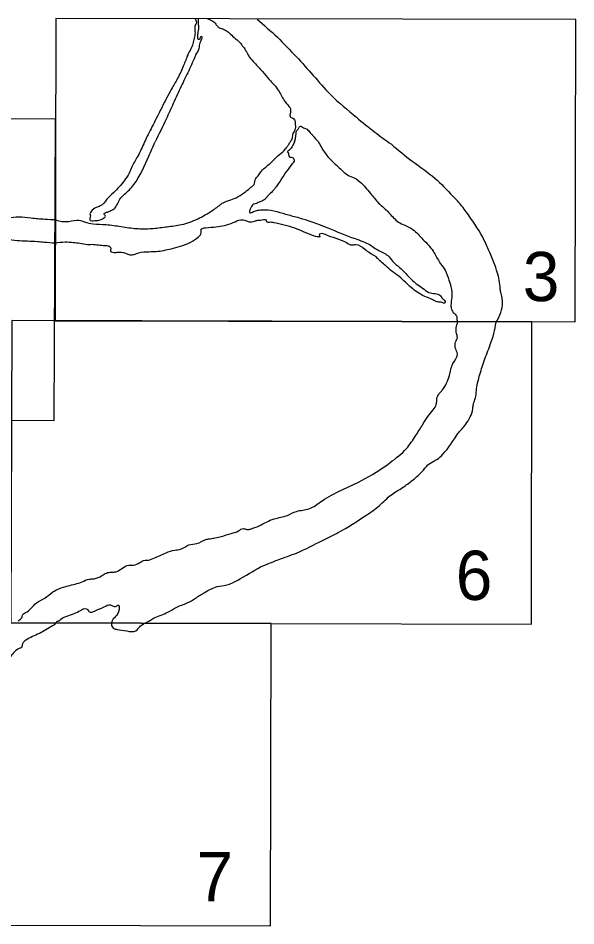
# Model space of a CAD drawing. Extents: x 3148686 to 3186545, y 916144 to 941516.
# Drawn here: x 3174711 to 3176037, y 918387 to 920544 of the extents above; entities that cross this region are included whole.
import ezdxf

# ---------------------------------------------------------------- set-up
doc = ezdxf.new("R2010")
doc.units = 0
doc.layers.add('V-ANNO-NPLT', color=7, linetype='Continuous')

msp = doc.modelspace()

# ---------------------------------------------------------------- linework, layer by layer
at = {"layer": 'V-ANNO-NPLT'}
for points in [[(3176036.1228912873, 919822.4712113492), (3176037.428891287, 920540.8912113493), (3174801.016891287, 920543.6782113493), (3174799.0828912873, 919825.2592113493), (3176036.1228912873, 919822.4712113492)], [(3173561.1928912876, 919589.6592113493), (3174796.979891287, 919588.3572113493), (3174800.3718912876, 920304.2032113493), (3173563.7538912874, 920308.0702113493), (3173561.1928912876, 919589.6592113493)], [(3174694.0118912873, 919107.1392113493), (3175931.6778912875, 919104.2592113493), (3175933.0358912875, 919822.6622113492), (3174695.9968912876, 919825.5412113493), (3174694.0118912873, 919107.1392113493)], [(3174072.8808912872, 918390.6002113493), (3175311.1728912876, 918387.1782113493), (3175312.843891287, 919105.5642113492), (3174694.0118912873, 919107.2742113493)]]:
    msp.add_lwpolyline(points, dxfattribs=at)
for points in [[(3175132.5218912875, 920542.8872113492), (3175133.1628912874, 920541.5342113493), (3175135.0408912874, 920533.0772113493), (3175131.7548912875, 920526.5002113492), (3175131.2858912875, 920519.9222113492), (3175131.7548912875, 920506.2972113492), (3175129.408891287, 920493.6122113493), (3175125.6538912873, 920479.9872113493), (3175118.144891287, 920464.0142113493), (3175112.0438912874, 920451.3282113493)], [(3175133.6328912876, 920457.4362113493), (3175141.610891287, 920472.0012113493), (3175143.9578912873, 920486.0952113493), (3175147.7118912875, 920494.5522113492), (3175148.6508912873, 920499.7202113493), (3175147.2428912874, 920500.1902113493), (3175144.4268912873, 920498.7802113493), (3175143.0188912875, 920495.4922113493), (3175140.2028912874, 920493.6122113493), (3175138.7948912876, 920495.4922113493), (3175138.7948912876, 920499.7202113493), (3175138.7948912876, 920503.4792113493), (3175139.7338912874, 920514.7542113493), (3175141.141891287, 920523.6812113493), (3175140.2028912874, 920528.8492113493), (3175139.7338912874, 920534.4872113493), (3175140.2028912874, 920538.7152113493), (3175139.7338912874, 920542.0042113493), (3175139.2648912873, 920544.3532113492), (3175139.2598912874, 920544.4462113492)], [(3175160.4308912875, 920543.4462113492), (3175167.8928912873, 920540.1252113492), (3175174.462891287, 920537.3062113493), (3175178.2178912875, 920534.0172113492), (3175183.8498912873, 920526.9702113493), (3175189.4808912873, 920521.8022113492), (3175199.8058912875, 920518.0432113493), (3175208.7228912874, 920512.8752113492), (3175219.0478912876, 920503.9482113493), (3175231.7198912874, 920492.6732113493), (3175238.7598912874, 920486.5652113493), (3175242.0448912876, 920481.8672113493), (3175246.7378912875, 920475.7592113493), (3175252.8388912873, 920467.3022113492), (3175256.593891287, 920460.2552113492), (3175260.3478912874, 920452.2682113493)], [(3175279.252891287, 920542.2832113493), (3175327.7588912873, 920498.9082113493), (3175372.5578912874, 920452.9942113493), (3175413.0888912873, 920408.1482113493), (3175453.6208912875, 920363.3012113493), (3175515.485891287, 920308.8442113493), (3175559.2178912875, 920273.6082113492), (3175598.6828912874, 920244.7782113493)], [(3175114.965891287, 920457.4032113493), (3175104.5348912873, 920431.5962113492), (3175090.4558912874, 920401.5272113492), (3175075.4368912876, 920375.2172113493), (3175064.1738912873, 920354.5452113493), (3175050.093891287, 920326.3562113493), (3175029.4438912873, 920285.9512113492), (3175011.6098912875, 920250.2452113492)], [(3175133.6888912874, 920457.5382113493), (3175116.7368912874, 920419.3812113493), (3175098.9028912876, 920382.7342113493), (3175080.1308912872, 920341.3902113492), (3175063.2348912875, 920304.7442113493), (3175036.9538912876, 920250.2452113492)], [(3175260.3478912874, 920452.2682113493), (3175273.4888912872, 920438.1732113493), (3175292.2618912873, 920417.5012113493), (3175308.2178912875, 920398.7082113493), (3175329.806891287, 920373.3382113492), (3175343.8868912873, 920348.9072113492), (3175355.1498912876, 920334.8132113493), (3175357.965891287, 920331.0542113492), (3175357.965891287, 920316.9602113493), (3175357.965891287, 920310.3822113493), (3175364.5358912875, 920306.6232113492), (3175368.2908912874, 920302.8652113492), (3175370.1678912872, 920296.2872113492), (3175370.1678912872, 920290.6502113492), (3175371.1068912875, 920287.8312113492), (3175370.1678912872, 920281.2532113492), (3175367.3518912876, 920274.6762113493), (3175364.5358912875, 920269.9772113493), (3175362.658891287, 920258.7022113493), (3175357.965891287, 920250.2452113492)], [(3175368.2908912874, 920250.2452113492), (3175371.1068912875, 920260.5812113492), (3175372.0458912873, 920269.0382113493), (3175372.9838912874, 920275.6152113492), (3175375.7998912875, 920279.3742113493), (3175379.5548912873, 920285.0122113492), (3175382.3698912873, 920287.8312113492), (3175385.1858912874, 920286.8912113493), (3175389.8798912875, 920284.0722113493), (3175398.326891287, 920280.3132113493), (3175405.8358912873, 920271.8572113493), (3175411.4678912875, 920266.2192113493), (3175416.1608912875, 920260.5812113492), (3175418.9768912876, 920256.8222113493), (3175425.5478912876, 920250.2452113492)], [(3175011.6098912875, 920250.2452113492), (3174995.6538912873, 920216.4182113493), (3174981.573891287, 920191.0472113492), (3174975.0038912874, 920176.0132113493), (3174963.7398912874, 920158.1602113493), (3174938.3968912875, 920129.9712113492), (3174922.4398912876, 920113.9972113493), (3174906.4838912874, 920098.0232113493), (3174897.0968912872, 920094.2642113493), (3174884.894891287, 920084.8682113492), (3174882.0788912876, 920079.2302113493), (3174883.0178912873, 920074.5322113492), (3174882.0788912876, 920068.8942113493), (3174882.0788912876, 920065.1352113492), (3174893.3428912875, 920063.2562113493), (3174906.4838912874, 920065.1352113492), (3174913.9928912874, 920068.8942113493), (3174918.6858912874, 920073.5922113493), (3174916.8078912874, 920077.3512113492), (3174915.8698912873, 920080.1702113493), (3174921.5018912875, 920082.9892113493), (3174929.0108912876, 920085.8082113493), (3174939.3358912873, 920091.4452113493), (3174953.414891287, 920113.9972113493), (3174975.9418912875, 920136.5482113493), (3174986.266891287, 920148.7642113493), (3175021.9348912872, 920216.4182113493), (3175036.9538912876, 920250.2452113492)], [(3175368.2908912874, 920250.2452113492), (3175360.3128912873, 920235.6802113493), (3175354.6808912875, 920230.0432113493), (3175351.8648912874, 920227.2242113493), (3175353.7418912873, 920222.5262113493), (3175354.6808912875, 920217.8272113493), (3175357.4968912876, 920214.0692113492), (3175360.3128912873, 920214.0692113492), (3175365.0058912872, 920212.1892113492), (3175367.8218912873, 920206.5522113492), (3175363.127891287, 920198.0952113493), (3175324.644891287, 920143.5962113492), (3175316.1968912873, 920133.2592113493), (3175304.9328912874, 920121.9842113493), (3175300.2398912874, 920116.3462113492), (3175294.607891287, 920111.6482113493), (3175286.1608912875, 920107.8892113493), (3175277.712891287, 920104.1312113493), (3175267.3878912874, 920099.4322113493), (3175264.5718912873, 920093.7952113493), (3175261.7558912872, 920086.2772113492), (3175261.7558912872, 920082.5192113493), (3175268.326891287, 920083.4582113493), (3175278.6518912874, 920087.2172113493), (3175290.8538912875, 920089.0962113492), (3175347.1718912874, 920078.7602113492), (3175375.3308912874, 920071.2432113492), (3175447.604891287, 920045.8732113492), (3175512.3708912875, 920020.5022113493), (3175548.0388912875, 920005.4682113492), (3175560.2408912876, 919997.0112113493)], [(3175272.5498912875, 920148.7642113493), (3175276.7738912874, 920163.3282113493), (3175283.3448912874, 920171.7852113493), (3175289.914891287, 920181.1812113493), (3175300.2398912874, 920190.5782113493), (3175319.9508912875, 920208.4312113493), (3175333.0918912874, 920220.6462113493), (3175347.1718912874, 920233.8012113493), (3175349.9878912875, 920237.5602113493), (3175354.6808912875, 920244.1372113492), (3175358.6748912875, 920251.5222113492)], [(3175425.5478912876, 920250.2452113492), (3175441.9738912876, 920222.5262113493), (3175458.8688912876, 920203.7332113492), (3175484.2118912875, 920180.2422113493), (3175494.536891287, 920171.7852113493), (3175510.4938912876, 920165.2072113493), (3175527.3888912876, 920152.0522113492), (3175536.7758912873, 920142.6562113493), (3175548.9778912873, 920127.6222113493), (3175567.7508912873, 920105.0702113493)], [(3175598.6828912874, 920244.7782113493), (3175648.4728912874, 920204.6722113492), (3175701.9748912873, 920164.2682113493), (3175744.6828912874, 920121.5142113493)], [(3174801.0798912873, 920064.7692113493), (3174815.4358912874, 920061.3772113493), (3174831.3928912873, 920061.3772113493), (3174856.735891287, 920064.1962113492), (3174868.9378912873, 920060.4372113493), (3174889.587891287, 920055.7392113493), (3174920.5628912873, 920053.8602113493), (3174956.2308912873, 920049.1612113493), (3174992.837891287, 920044.4632113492), (3175028.5058912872, 920044.4632113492), (3175061.357891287, 920048.2222113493), (3175095.1488912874, 920052.9202113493), (3175133.6328912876, 920065.1352113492), (3175169.3008912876, 920084.8682113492), (3175191.8278912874, 920100.8422113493), (3175198.397891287, 920105.5402113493), (3175212.4778912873, 920111.1782113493), (3175229.3728912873, 920117.7552113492), (3175248.1458912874, 920129.0312113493), (3175262.2248912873, 920140.3072113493), (3175272.5498912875, 920148.7642113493)], [(3175847.5928912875, 919821.8102113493), (3175859.195891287, 919845.2592113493), (3175862.9508912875, 919868.7502113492), (3175861.0728912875, 919883.7842113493), (3175858.2568912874, 919895.0602113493), (3175857.3188912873, 919906.3362113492), (3175848.8708912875, 919945.8012113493), (3175830.0978912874, 919993.7232113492), (3175816.0188912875, 920023.7912113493), (3175776.5958912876, 920083.9282113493), (3175755.945891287, 920110.2382113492), (3175744.6828912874, 920121.5142113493)], [(3175567.7508912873, 920105.0702113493), (3175593.093891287, 920081.5792113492), (3175615.6208912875, 920059.9672113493), (3175630.6388912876, 920052.4502113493), (3175649.411891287, 920042.1142113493), (3175673.8158912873, 920018.6232113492), (3175698.2198912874, 919990.4342113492), (3175712.2998912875, 919966.0032113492), (3175726.3788912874, 919945.3312113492), (3175735.7658912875, 919921.8402113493), (3175740.4588912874, 919905.8662113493), (3175742.3358912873, 919881.4352113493), (3175740.4588912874, 919862.6422113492), (3175741.397891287, 919853.2462113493), (3175747.9678912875, 919842.9102113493), (3175754.5378912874, 919834.4532113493), (3175754.5378912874, 919829.7552113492), (3175756.7098912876, 919822.8552113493)], [(3174801.0798912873, 920064.7702113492), (3174774.8388912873, 920066.1522113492), (3174741.6918912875, 920068.9172113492), (3174712.6878912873, 920071.6832113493), (3174687.8278912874, 920068.9172113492), (3174669.8738912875, 920067.5352113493), (3174654.6808912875, 920062.0042113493), (3174647.7758912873, 920060.6222113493), (3174639.4888912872, 920062.0042113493), (3174553.8598912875, 920067.5352113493), (3174519.3318912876, 920066.1522113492), (3174483.4228912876, 920066.1522113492), (3174443.3708912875, 920068.9172113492), (3174400.5558912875, 920071.6832113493), (3174360.5038912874, 920075.8302113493), (3174274.874891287, 920071.6832113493), (3174225.1538912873, 920064.7702113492), (3174196.1508912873, 920063.3872113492), (3174151.9548912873, 920057.8562113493), (3174102.2348912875, 920057.8562113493), (3174063.5638912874, 920057.8562113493), (3174038.7038912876, 920057.8562113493), (3174013.843891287, 920060.6222113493), (3173969.647891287, 920053.7092113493)], [(3174798.9778912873, 920010.2432113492), (3174822.9448912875, 920012.5152113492), (3174842.6558912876, 920011.5762113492), (3174857.6748912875, 920009.6972113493), (3174876.4468912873, 920006.8782113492), (3174890.5268912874, 920006.8782113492), (3174906.4838912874, 920004.9982113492), (3174920.5628912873, 920004.0592113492), (3174929.948891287, 920001.2402113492), (3174931.826891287, 919997.4812113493), (3174930.8878912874, 919990.9042113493), (3174936.519891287, 919988.0852113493), (3174946.8448912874, 919988.0852113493), (3174966.5558912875, 919986.2052113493), (3174974.0648912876, 919982.4472113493), (3174985.3288912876, 919982.4472113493), (3174992.837891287, 919985.2662113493), (3175039.7688912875, 919989.9642113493), (3175075.4368912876, 919996.5422113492), (3175097.0258912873, 920002.1792113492), (3175120.4918912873, 920011.5762113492), (3175140.2028912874, 920024.7312113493), (3175145.8348912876, 920031.3082113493), (3175146.7738912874, 920042.5842113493), (3175157.0988912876, 920046.3432113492), (3175181.502891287, 920048.2222113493), (3175202.1528912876, 920051.9802113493), (3175222.8028912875, 920058.5582113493), (3175240.6368912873, 920065.1352113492), (3175251.8998912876, 920063.2562113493), (3175260.3478912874, 920060.4372113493), (3175273.4888912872, 920062.3162113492), (3175280.9978912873, 920064.1962113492)], [(3175280.9978912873, 920064.1962113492), (3175294.607891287, 920065.6052113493), (3175299.3008912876, 920065.6052113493), (3175302.1168912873, 920060.9072113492), (3175308.6878912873, 920059.9672113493), (3175319.0128912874, 920059.0282113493), (3175368.7598912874, 920045.8732113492), (3175410.0598912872, 920028.9592113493), (3175419.445891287, 920026.1402113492), (3175426.016891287, 920025.2012113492), (3175429.7708912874, 920025.2012113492), (3175427.8938912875, 920029.8992113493), (3175430.7098912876, 920032.7182113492), (3175441.0348912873, 920030.8382113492), (3175491.7208912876, 920011.1062113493), (3175504.8618912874, 920005.4682113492), (3175514.2478912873, 920006.4082113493), (3175535.8368912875, 919995.1322113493), (3175558.3638912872, 919980.0982113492)], [(3174433.0118912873, 920000.4782113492), (3174475.1358912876, 919998.4042113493), (3174512.4268912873, 919999.7862113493), (3174545.5728912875, 920003.9342113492), (3174585.6258912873, 920009.4652113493), (3174633.9648912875, 920014.9952113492), (3174665.729891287, 920020.5262113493), (3174683.6848912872, 920019.1432113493), (3174708.5448912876, 920016.3782113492), (3174733.4048912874, 920014.9952113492), (3174756.8838912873, 920013.6132113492), (3174773.4568912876, 920012.2302113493), (3174798.9778912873, 920010.2442113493)], [(3175560.2408912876, 919997.0112113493), (3175578.0748912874, 919987.6152113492), (3175590.2778912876, 919980.0982113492), (3175601.5408912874, 919966.9432113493), (3175618.4368912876, 919951.9082113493), (3175638.147891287, 919932.1762113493), (3175657.8588912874, 919913.3832113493), (3175672.8768912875, 919903.0472113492), (3175687.8958912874, 919892.7112113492), (3175702.9138912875, 919889.8922113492), (3175714.1768912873, 919886.1342113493), (3175720.7478912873, 919877.6772113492), (3175726.3788912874, 919871.0992113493), (3175726.3788912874, 919868.2802113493), (3175716.053891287, 919869.2202113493), (3175707.6068912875, 919870.1602113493), (3175699.158891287, 919873.9182113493), (3175671.9388912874, 919886.1342113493), (3175642.840891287, 919906.8062113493), (3175613.7438912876, 919933.1162113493), (3175596.8478912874, 919945.3312113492), (3175582.7688912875, 919958.4862113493), (3175571.5048912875, 919967.8822113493), (3175565.8728912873, 919973.5202113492), (3175558.3638912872, 919980.0982113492)], [(3175656.4248912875, 919552.0002113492), (3175673.1388912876, 919578.1442113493), (3175685.6748912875, 919598.0142113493), (3175698.2108912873, 919613.7012113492), (3175705.522891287, 919626.2502113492), (3175706.5678912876, 919635.6622113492), (3175707.6118912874, 919644.0282113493), (3175714.9248912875, 919654.4862113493), (3175720.147891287, 919660.7612113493), (3175736.8618912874, 919695.2712113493), (3175745.218891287, 919723.5072113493), (3175755.6658912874, 919746.5142113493), (3175751.4868912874, 919759.0642113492), (3175751.4868912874, 919774.7502113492), (3175755.6658912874, 919785.2082113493), (3175753.576891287, 919794.6202113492), (3175756.7098912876, 919822.8562113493)], [(3175756.7098912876, 919557.2292113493), (3175775.5138912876, 919579.1902113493), (3175792.2278912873, 919615.7922113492), (3175793.272891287, 919624.1592113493), (3175797.4508912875, 919637.7542113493), (3175802.6738912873, 919672.2642113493), (3175807.897891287, 919693.1802113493), (3175819.3888912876, 919729.7822113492), (3175834.0138912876, 919768.4762113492), (3175842.3708912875, 919794.6202113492), (3175847.593891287, 919821.8102113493)], [(3175287.6678912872, 919240.3592113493), (3175329.4528912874, 919257.0912113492), (3175374.3728912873, 919273.8242113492), (3175434.9618912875, 919303.1052113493), (3175472.5688912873, 919321.9292113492), (3175538.3808912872, 919362.7152113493), (3175569.7198912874, 919385.7222113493), (3175598.9698912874, 919411.8662113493), (3175625.0858912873, 919428.5982113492), (3175649.1128912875, 919446.3772113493), (3175675.2288912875, 919470.4292113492), (3175689.8538912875, 919486.1162113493), (3175706.5678912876, 919495.5282113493), (3175721.1928912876, 919508.0772113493), (3175756.7098912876, 919557.2292113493)], [(3175284.533891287, 919337.6162113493), (3175320.0518912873, 919354.3482113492), (3175351.3908912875, 919362.7152113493), (3175373.3278912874, 919372.1262113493), (3175402.5778912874, 919378.4012113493), (3175433.9168912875, 919397.2252113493), (3175527.9348912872, 919445.3312113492), (3175595.8358912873, 919488.2082113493), (3175634.4878912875, 919521.6722113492), (3175656.4248912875, 919552.0002113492)], [(3174711.2518912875, 919111.5992113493), (3174718.3398912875, 919118.0032113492), (3174720.428891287, 919120.0942113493), (3174721.4738912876, 919125.3232113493), (3174728.7858912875, 919131.5982113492), (3174741.3218912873, 919141.0102113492), (3174754.9018912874, 919154.6052113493), (3174774.7508912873, 919166.1092113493), (3174793.553891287, 919180.7492113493), (3174808.178891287, 919188.0702113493), (3174830.0318912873, 919195.3372113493), (3174863.5448912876, 919204.8022113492), (3174880.2588912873, 919211.0772113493), (3174891.749891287, 919212.1232113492), (3174910.5528912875, 919219.4432113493), (3174920.999891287, 919225.7182113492), (3174933.5358912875, 919227.8092113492), (3174943.9818912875, 919228.8552113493), (3174974.2758912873, 919244.5422113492), (3174985.766891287, 919244.5422113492), (3175000.391891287, 919250.8162113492), (3175012.9278912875, 919256.0452113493), (3175018.1508912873, 919256.0452113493), (3175034.0978912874, 919260.7422113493), (3175063.070891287, 919273.8242113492), (3175083.962891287, 919280.0982113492), (3175097.5438912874, 919282.1902113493), (3175117.391891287, 919292.6482113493), (3175136.1948912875, 919295.7852113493), (3175157.5048912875, 919305.1522113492), (3175167.533891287, 919307.2882113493), (3175180.0698912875, 919309.3802113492), (3175194.6948912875, 919312.5172113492), (3175217.6768912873, 919319.8382113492), (3175235.4358912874, 919326.1122113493), (3175246.9268912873, 919331.3412113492), (3175255.283891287, 919329.2502113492), (3175263.6408912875, 919330.2952113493), (3175284.533891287, 919337.6162113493)], [(3174807.5848912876, 919111.5992113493), (3174818.624891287, 919120.0942113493), (3174826.9818912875, 919123.2322113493), (3174844.7408912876, 919129.5062113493), (3174859.3658912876, 919136.8272113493), (3174869.8128912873, 919141.0102113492), (3174875.0358912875, 919139.9642113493), (3174878.1698912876, 919135.7812113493), (3174884.4378912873, 919132.6442113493), (3174895.928891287, 919136.8272113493), (3174915.7768912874, 919145.1932113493), (3174930.854891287, 919150.1192113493), (3174942.9368912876, 919146.2392113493), (3174949.4068912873, 919149.7152113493), (3174951.2938912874, 919138.9182113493), (3174942.9368912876, 919122.1862113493), (3174933.6778912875, 919110.1502113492), (3174938.1148912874, 919094.0002113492), (3174946.5838912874, 919091.5782113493), (3174969.570891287, 919087.9452113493), (3174990.945891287, 919088.3482113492), (3175002.4818912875, 919100.2252113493), (3175017.1068912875, 919108.5912113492), (3175034.8648912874, 919119.0492113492), (3175067.2488912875, 919132.6442113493), (3175087.0968912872, 919144.1472113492), (3175113.212891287, 919154.6052113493), (3175133.0608912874, 919166.1092113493), (3175154.9988912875, 919179.7042113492), (3175184.2488912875, 919193.2992113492), (3175207.2308912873, 919197.4822113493), (3175233.3468912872, 919208.9852113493), (3175287.6678912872, 919240.3592113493)], [(3174807.5848912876, 919111.5992113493), (3174801.3288912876, 919108.2282113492), (3174799.0818912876, 919104.4792113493), (3174793.0918912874, 919099.9812113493), (3174761.6388912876, 919081.9892113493), (3174729.4378912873, 919066.2462113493), (3174725.6938912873, 919063.2472113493), (3174721.9498912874, 919057.2492113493), (3174720.451891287, 919052.7512113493), (3174719.7028912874, 919049.7532113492), (3174713.7118912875, 919046.0042113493), (3174693.4928912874, 919028.0122113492), (3174677.766891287, 919010.7692113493), (3174667.2828912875, 919001.0242113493), (3174658.2968912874, 918993.5272113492), (3174650.0588912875, 918986.0302113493), (3174633.5838912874, 918964.2892113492), (3174626.8448912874, 918953.0442113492), (3174624.5978912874, 918945.5472113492), (3174623.8488912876, 918941.7992113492), (3174620.104891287, 918935.0522113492), (3174614.8628912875, 918932.0532113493), (3174611.1188912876, 918931.3042113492), (3174606.624891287, 918930.5542113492), (3174603.6298912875, 918926.0562113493), (3174578.9178912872, 918891.5712113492), (3174574.4238912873, 918881.0752113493), (3174567.8108912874, 918869.7812113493)]]:
    msp.add_spline(points, degree=3, dxfattribs=at)

# ---------------------------------------------------------------- texts
for s, p in [('3', (3175911.3138912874, 919871.9622113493)), ('6', (3175751.8288912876, 919161.7842113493)), ('7', (3175135.2258912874, 918445.4142113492))]:
    msp.add_text(s, height=116.99999999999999, rotation=359.9396362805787, dxfattribs=at).set_placement(p)

doc.saveas('drawing.dxf')
